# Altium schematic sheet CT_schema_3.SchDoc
size 258 x 163 mm
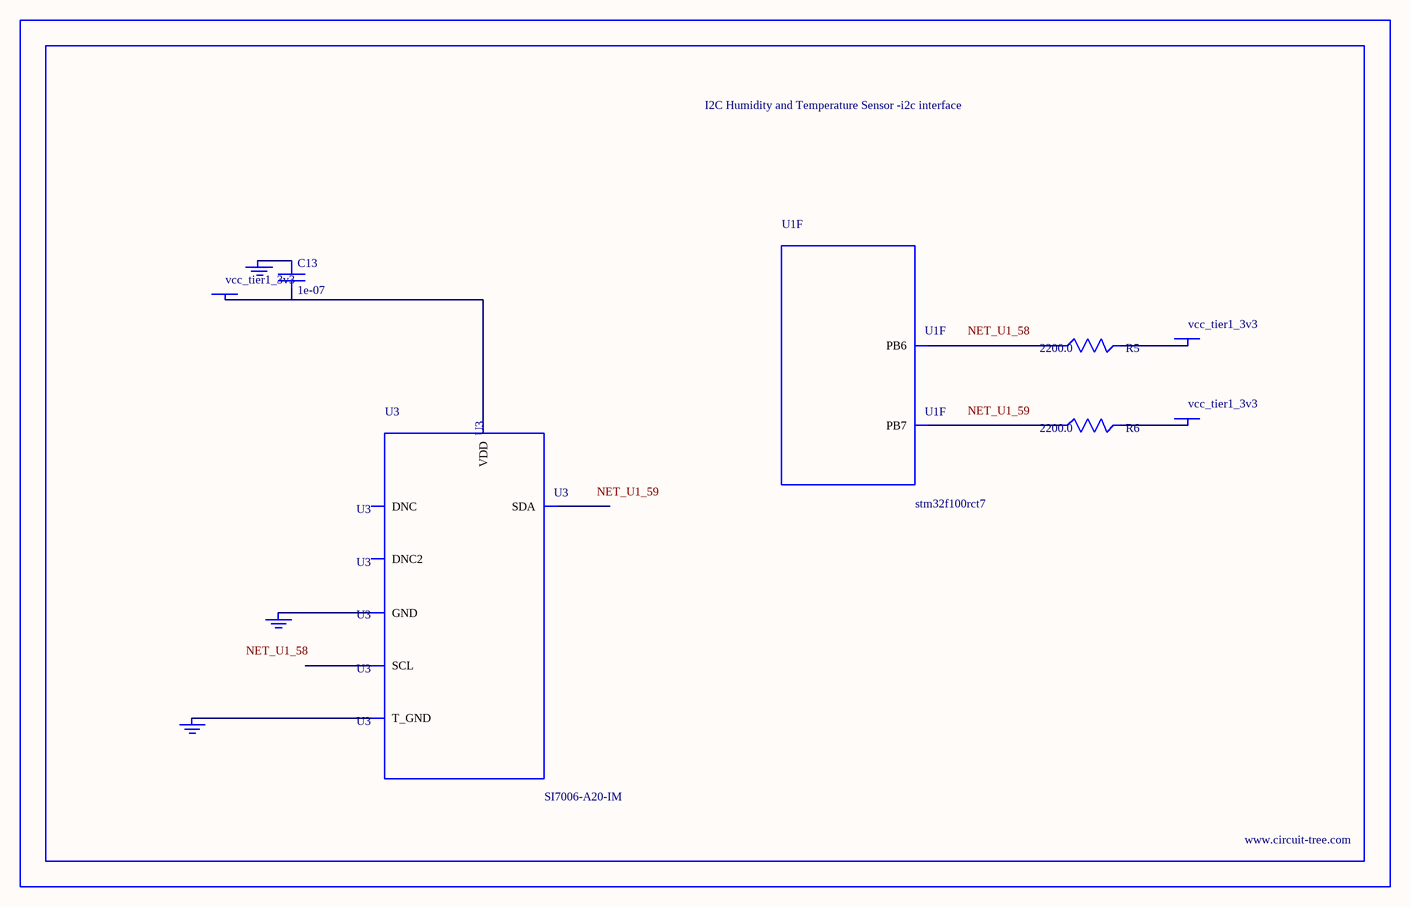
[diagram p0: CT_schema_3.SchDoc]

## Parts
BORDER2  (no value)
C13  1e-07  [C0402]
GND_INSTANCE_2_0  (no value)
GND_INSTANCE_2_1  (no value)
GND_INSTANCE_2_2  (no value)
POWER_INSTANCE_2_0  vcc_tier1_3v3
POWER_INSTANCE_2_1  vcc_tier1_3v3
POWER_INSTANCE_2_2  vcc_tier1_3v3
R5  2200.0  [R0603]
R6  2200.0  [R0603]
U1  stm32f100rct7  [LQFP64]  (part F of 6)
U3  SI7006-A20-IM  [DFN-6]

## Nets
NetC13_1: C13.1 GND_INSTANCE_2_0.0(GND)
NetC13_2: C13.2 POWER_INSTANCE_2_0.0(PWR) U3.5(VDD)
NetGND_INSTANCE_2_1_0: GND_INSTANCE_2_1.0(GND) U3.7(T_GND)
NetGND_INSTANCE_2_2_0: GND_INSTANCE_2_2.0(GND) U3.2(GND)
NetPOWER_INSTANCE_2_1_0: POWER_INSTANCE_2_1.0(PWR) R5.2
NetPOWER_INSTANCE_2_2_0: POWER_INSTANCE_2_2.0(PWR) R6.2
NetR5_1: R5.1 U1.58(PB6)
NetR6_1: R6.1 U1.59(PB7)

Not connected (* = marked no-connect by the designer): U3 1(SDA) 3(DNC) 4(DNC2) 6(SCL)

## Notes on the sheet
- Labels drawn without touching a wire or pin: NET_U1_58, NET_U1_59

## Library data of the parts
BORDER2 = BORDER_PAGE2
C13 = C0402C104K3RACTU
GND_INSTANCE_2_0-GND_INSTANCE_2_2 = GND
POWER_INSTANCE_2_0-POWER_INSTANCE_2_2 = PWR
R5 R6 = RC0603JR-072K2L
